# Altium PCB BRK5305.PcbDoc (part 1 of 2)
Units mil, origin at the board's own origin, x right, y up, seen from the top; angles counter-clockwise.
Board outline 4724.41 x 3149.61 mil, 4 copper layers (L1-Top, L2-Plane-1, L3-Plane-2, L4-Bottom), stack 60.6 mil thick; 66 components, 156 nets, 613 pads, 306 vias.
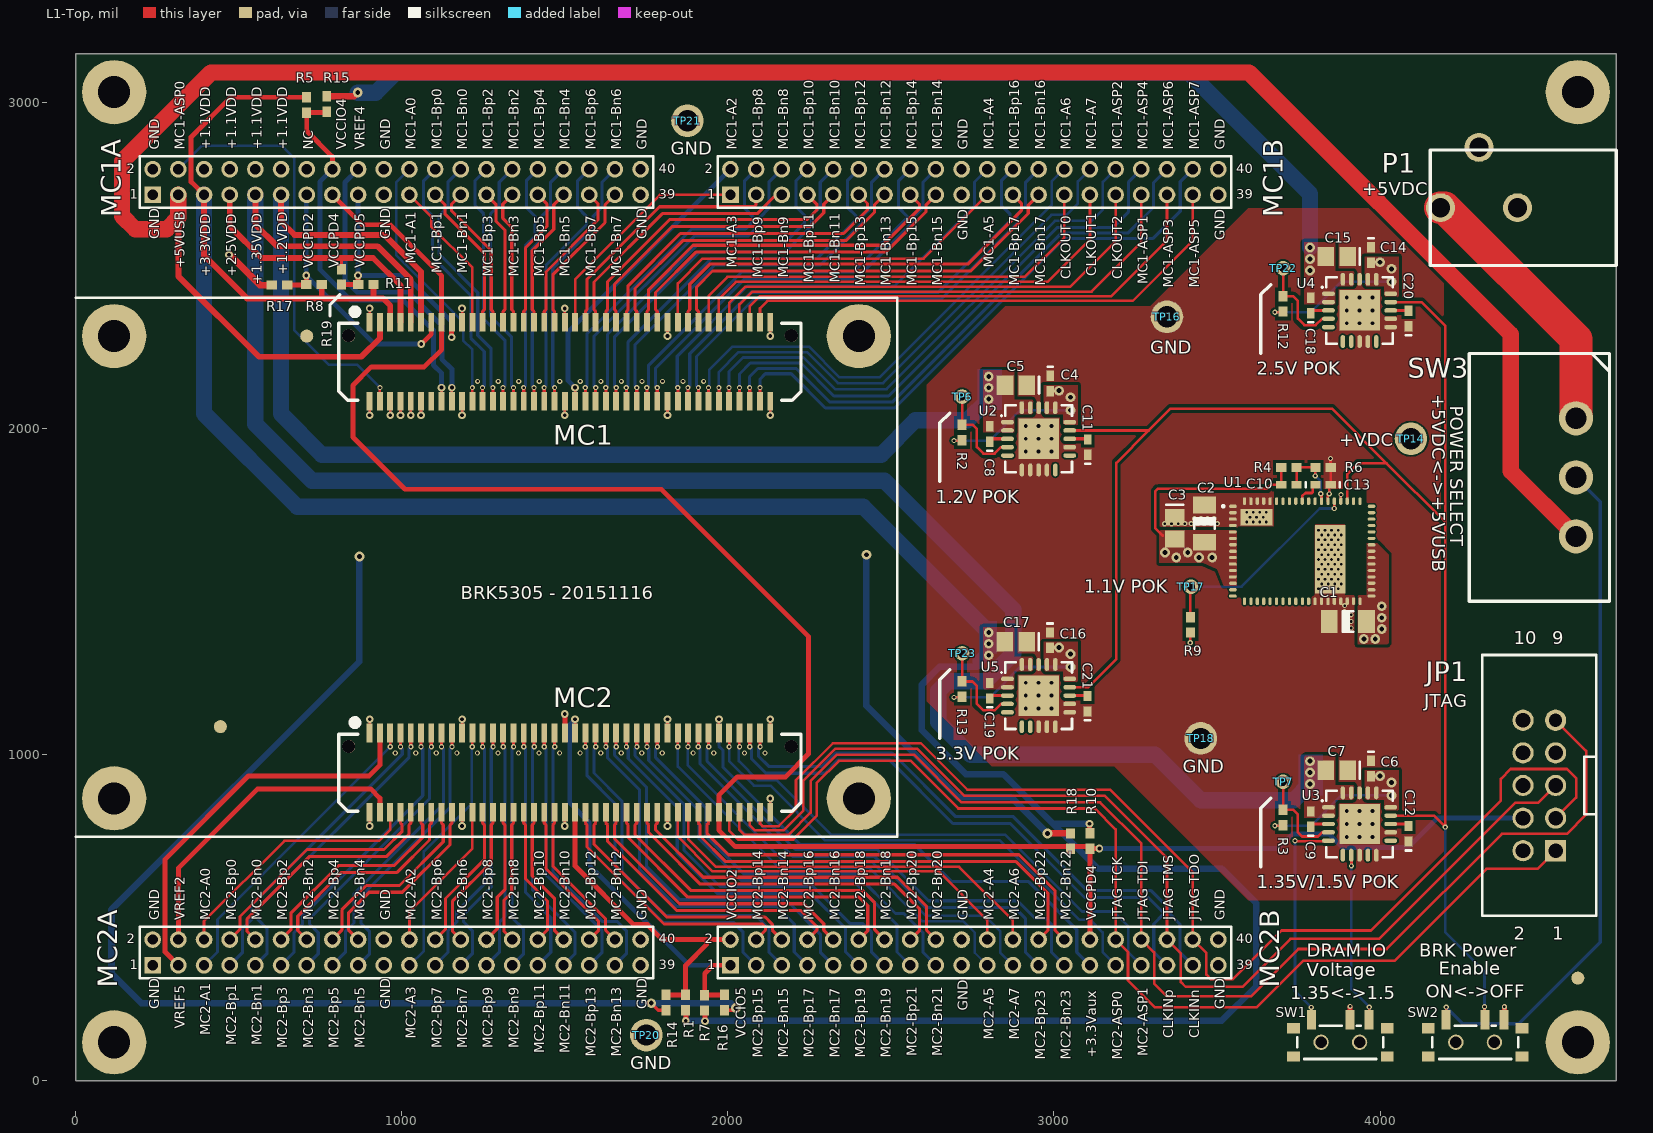
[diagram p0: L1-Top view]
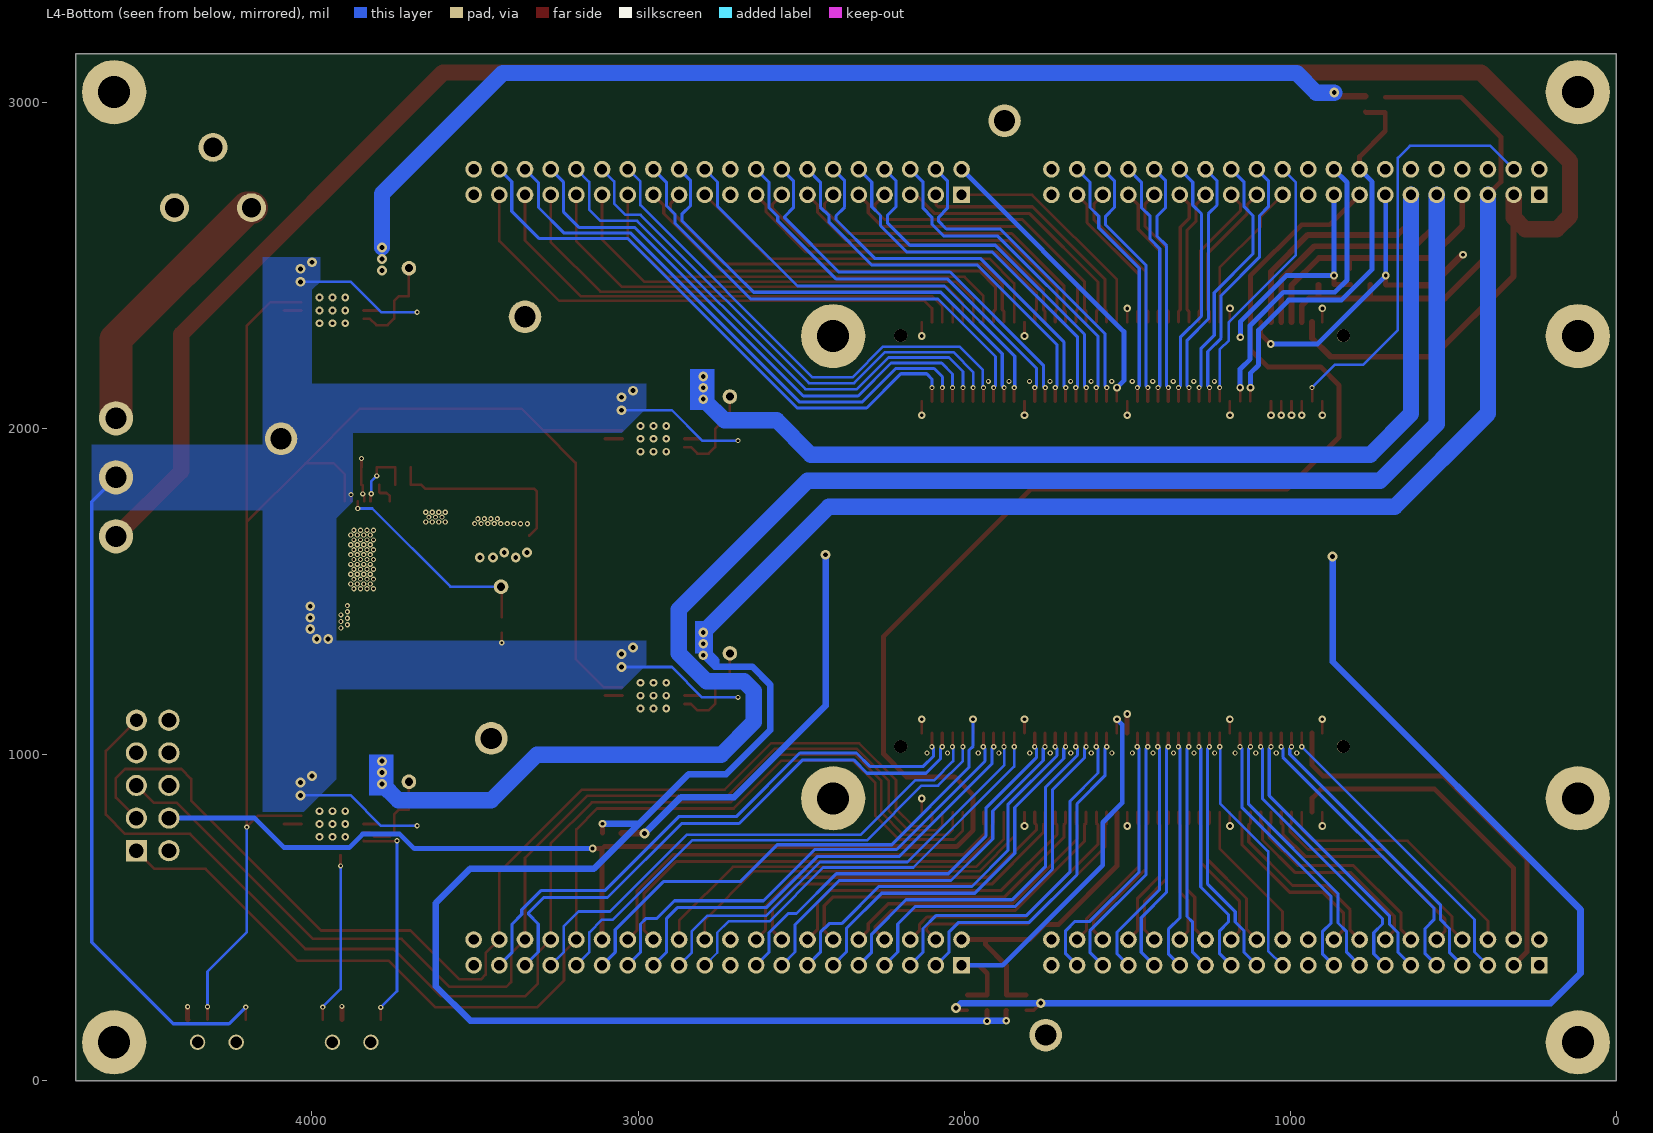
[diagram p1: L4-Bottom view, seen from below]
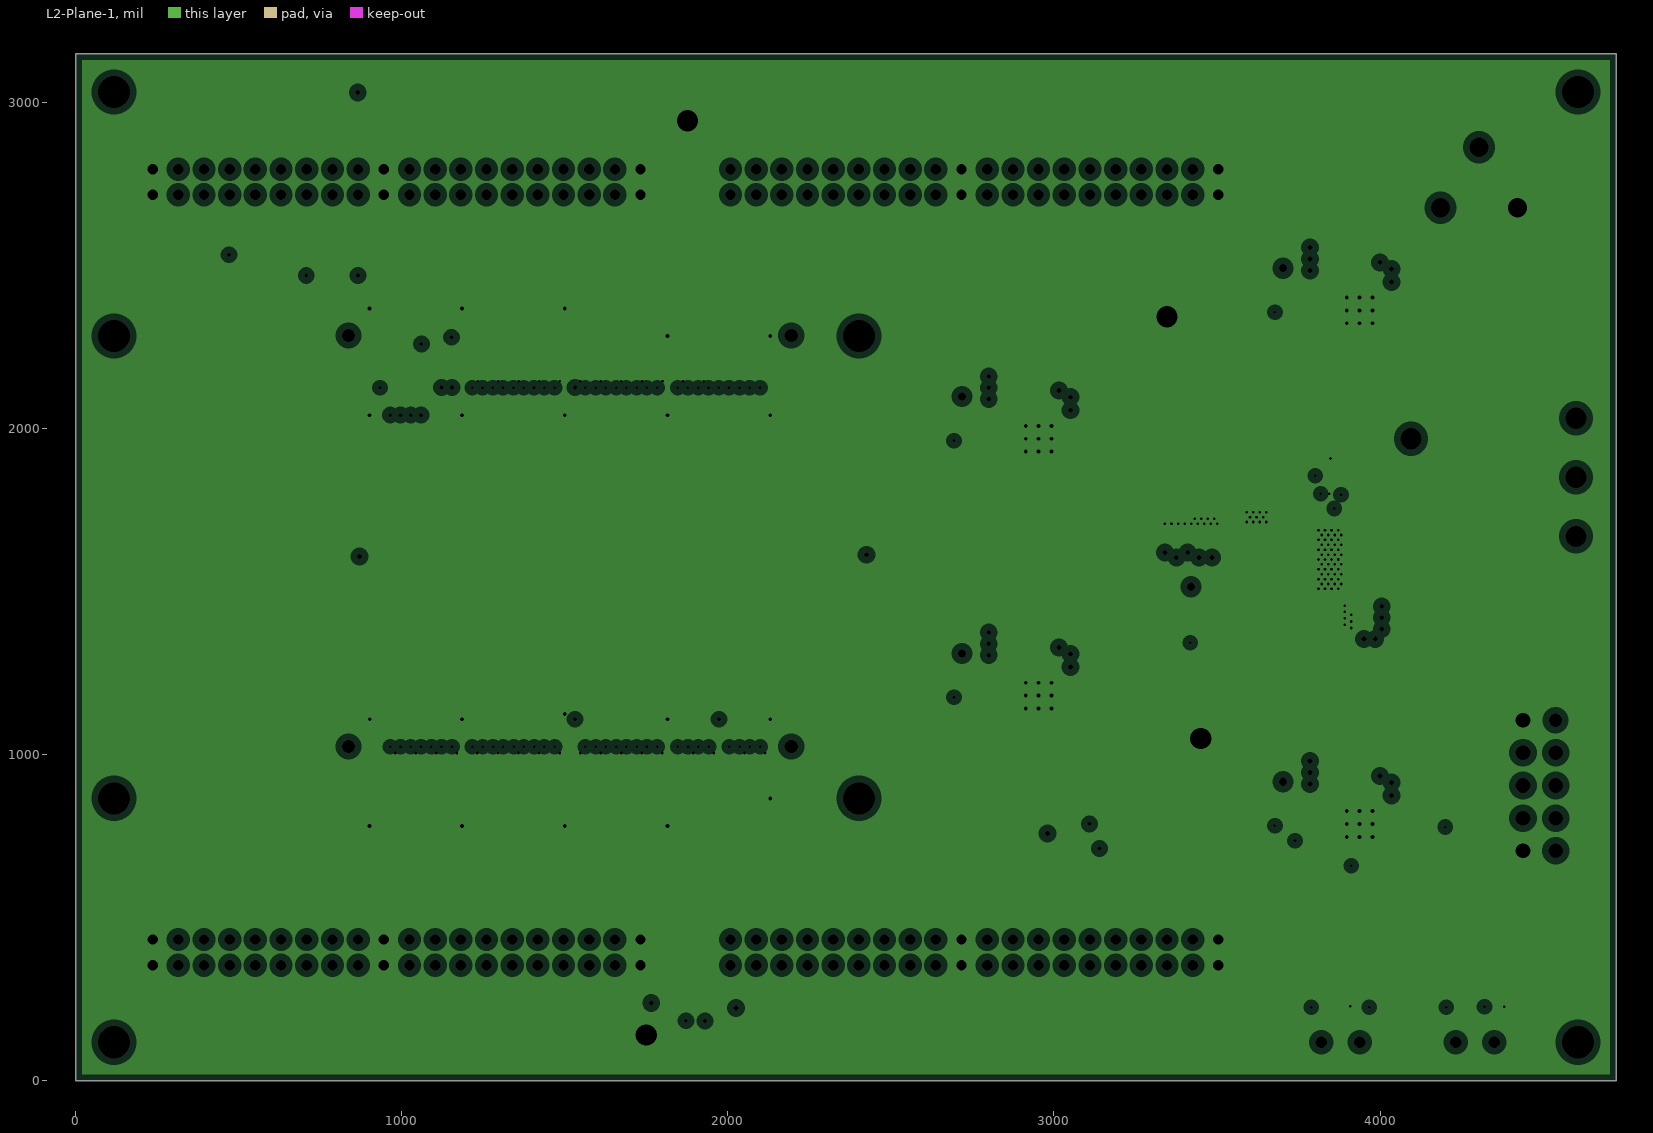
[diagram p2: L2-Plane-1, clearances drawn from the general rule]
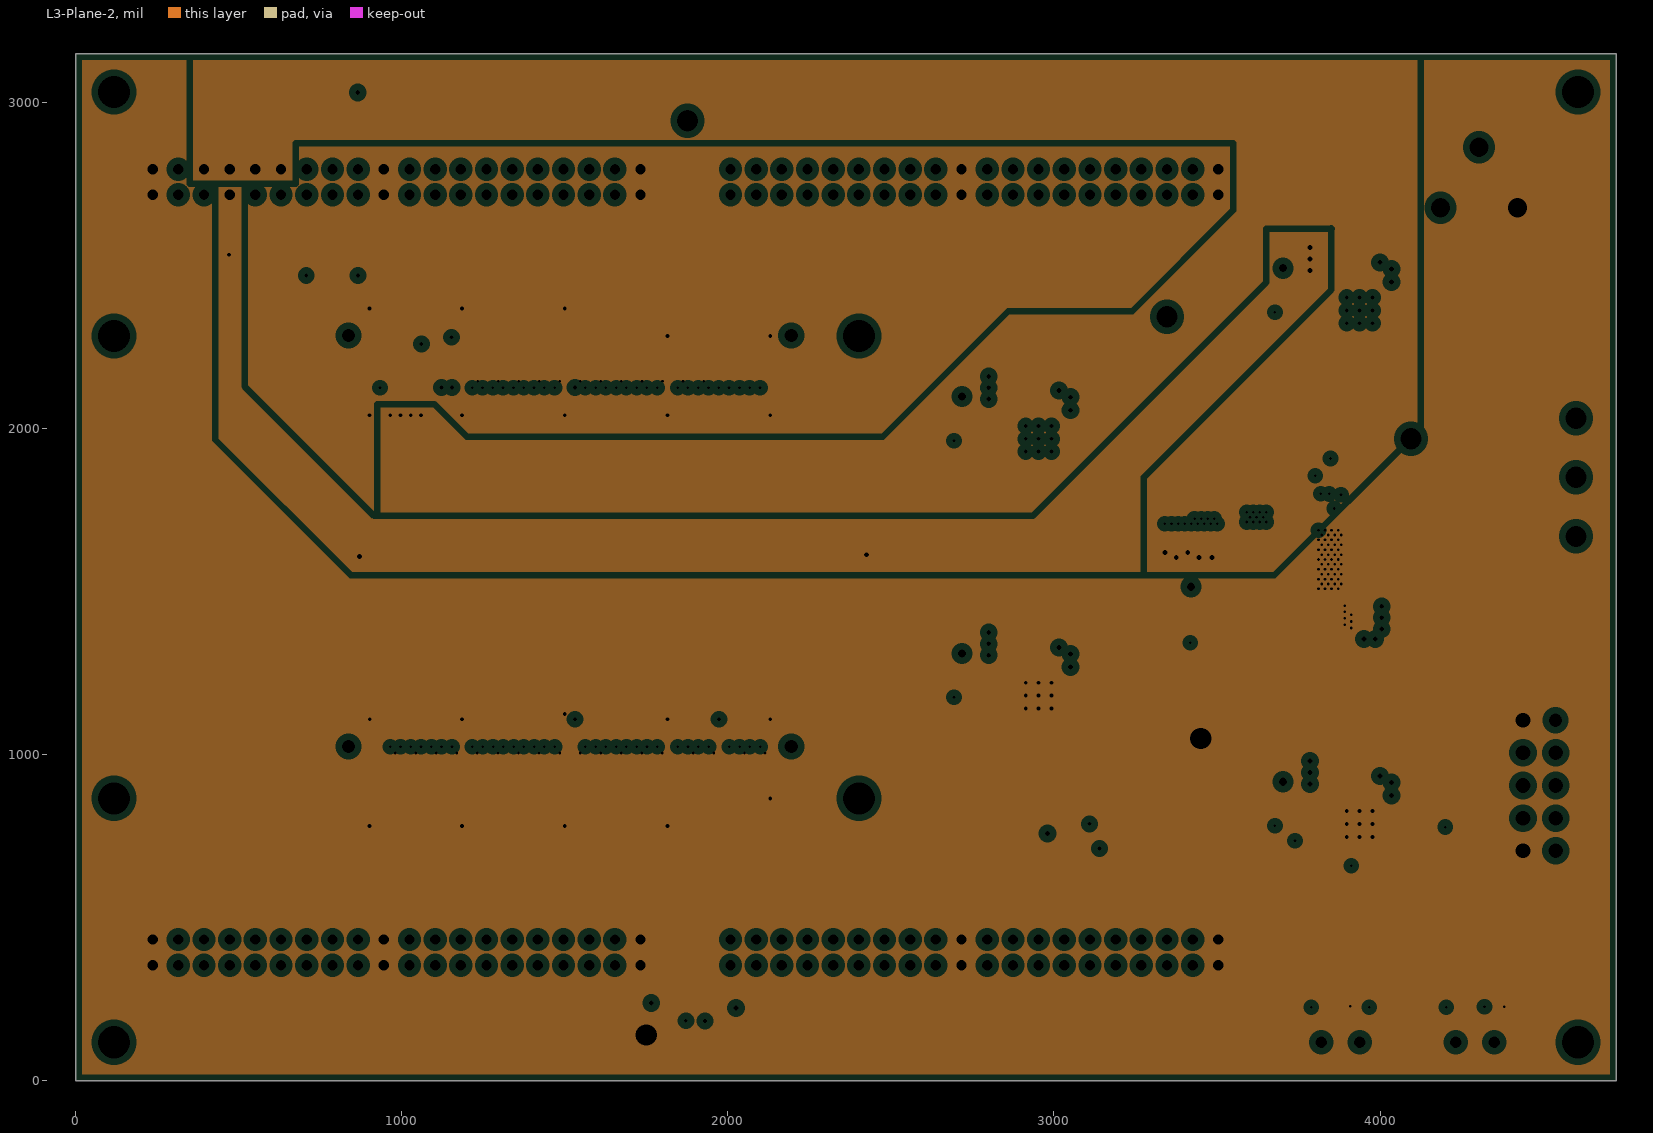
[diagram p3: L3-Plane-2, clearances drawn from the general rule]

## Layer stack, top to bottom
Top Solder: solder mask 0.4, Solder Resist, Dk 3.5
L1-Top: signal copper 2.1
Dielectric1: prepreg 7.3, 370HR, Dk 4.2
L2-Plane-1: plane copper 1.4, net DGND
Dielectric 3: core 39, 370HR, Dk 4.2
L3-Plane-2: plane copper 1.4, net (Multiple Nets)
Dielectric 2: prepreg 7.3, 370HR, Dk 4.2
L4-Bottom: signal copper 2.1
Bottom Solder: solder mask 0.4, Solder Resist, Dk 3.5

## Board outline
0,0 4724.41,0 4724.41,3149.61 0,3149.61

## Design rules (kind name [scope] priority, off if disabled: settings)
Clearance okxClearancePour [((InPolygon) AND (OnLayer('L1-Top') OR OnLayer('L2-Bottom')) ) vs ((InAnyNet) AND (OnLayer('L1-Top') OR OnLayer('L2-Bottom')) )] p1: gap=10
Clearance Fiducial [All vs ((Not PadIsPlated) And (HoleSize = 0))] p2: gap=25
Clearance [All] p3: gap=5
DiffPairsRouting okxDiffRouting100ohm [All] p1: maxlimit=11.5 minlimit=11.5 mostfreqgap=11.5 toplayer_minwidth=9.5 toplayer_maxwidth=9.5 toplayer_prefwidth=9.5 bottomlayer_minwidth=9.5 bottomlayer_maxwidth=9.5 bottomlayer_prefwidth=9.5 maxuncoupledlength=500
FabricationTestPointUsage TestPointUsage [All] p1: valid=0 allowmultiple=FALSE
FabricationTestpoint Testpoint [All] p1: side=3 testpointundercomponent=TRUE minsize=40 maxsize=100 preferedsize=60 minholesize=0 maxholesize=40 preferedholesize=32 testpointgrid=1 allowsidetop=TRUE allowsidebottom=TRUE usegrid=TRUE gridtolerance=0.01
HoleSize [All] p1: absolutevalues=TRUE maxlimit=100 minlimit=8 maxpercent=80.000 minpercent=20.000
PlaneClearance [All] p1: clearance=20
PlaneConnect [All] p1: planeconnectstyle=Direct reliefexpansion=20 reliefentries=4 reliefconductorwidth=10 reliefairgap=10
PolygonConnect "Via Connect" [IsVia] p1: connectstyle=Direct reliefconductorwidth=10 reliefentries=4 polygonreliefangle="90 Angle" airgapwidth=10
PolygonConnect [All] p2: connectstyle=Direct reliefconductorwidth=10 reliefentries=4 polygonreliefangle="90 Angle" airgapwidth=10
RoutingVias [All] p1: holewidth=8 width=16 viastyle="Through Hole" minholewidth=8 minwidth=16 maxholewidth=25 maxwidth=50
SolderMaskExpansion [All] p1: expansion=4
Width okWidth50ohm [All] p1: maxlimit=200 minlimit=8 preferedwidth=12 minimp=50.000000 maximp=50.000000 favimp=50.000000
24 further rules are at their usual default settings.

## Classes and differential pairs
net class okPower: +1.1VDD +1.2VDD +1.35VDD +2.5VDD +3.3VAUX +3.3VDD +5VDC +5VUSB +VDC DGND VCCIO2 VCCIO4 VCCIO5 VCCPD2 VCCPD4 VCCPD5 VREF2 VREF4 VREF5
net class okMC1-A: MC1-A0 MC1-A1 MC1-A2 MC1-A3 MC1-A4 MC1-A5 MC1-A6 MC1-A7
net class okMC1-ASP: MC1-ASP0 MC1-ASP1 MC1-ASP2 MC1-ASP3 MC1-ASP4 MC1-ASP5 MC1-ASP6 MC1-ASP7
net class okMC1-B: MC1-BN0 MC1-BN1 MC1-BN2 MC1-BN3 MC1-BN4 MC1-BN5 MC1-BN6 MC1-BN7 MC1-BN8 MC1-BN9 MC1-BN10 MC1-BN11 MC1-BN12 MC1-BN13 MC1-BN14 MC1-BN15 MC1-BN16 MC1-BN17 MC1-BP0 MC1-BP1 MC1-BP2 MC1-BP3 MC1-BP4 MC1-BP5 MC1-BP6 MC1-BP7 MC1-BP8 MC1-BP9 MC1-BP10 MC1-BP11 MC1-BP12 MC1-BP13 MC1-BP14 MC1-BP15 MC1-BP16 MC1-BP17
net class okMC-CLK: CLKINN CLKINP CLKOUT0 CLKOUT1 CLKOUT2
net class okJTAG: JTAG_TCK JTAG_TDI JTAG_TDO JTAG_TMS
net class okMC2-B: MC2-BN0 MC2-BN1 MC2-BN2 MC2-BN3 MC2-BN4 MC2-BN5 MC2-BN6 MC2-BN7 MC2-BN8 MC2-BN9 MC2-BN10 MC2-BN11 MC2-BN12 MC2-BN13 MC2-BN14 MC2-BN15 MC2-BN16 MC2-BN17 MC2-BN18 MC2-BN19 MC2-BN20 MC2-BN21 MC2-BN22 MC2-BN23 MC2-BP0 MC2-BP1 MC2-BP2 MC2-BP3 MC2-BP4 MC2-BP5 MC2-BP6 MC2-BP7 MC2-BP8 MC2-BP9 MC2-BP10 MC2-BP11 MC2-BP12 MC2-BP13 MC2-BP14 MC2-BP15 MC2-BP16 MC2-BP17 MC2-BP18 MC2-BP19 MC2-BP20 MC2-BP21 MC2-BP22 MC2-BP23
net class okMC2-ASP: MC2-ASP0 MC2-ASP1
differential pair D_CLKIN: +CLKINP -CLKINN
differential pair D_MC2-B23: +MC2-BP23 -MC2-BN23
differential pair D_MC2-B22: +MC2-BP22 -MC2-BN22
differential pair D_MC2-B21: +MC2-BP21 -MC2-BN21
differential pair D_MC2-B20: +MC2-BP20 -MC2-BN20
differential pair D_MC2-B19: +MC2-BP19 -MC2-BN19
differential pair D_MC2-B18: +MC2-BP18 -MC2-BN18
differential pair D_MC2-B17: +MC2-BP17 -MC2-BN17
differential pair D_MC2-B16: +MC2-BP16 -MC2-BN16
differential pair D_MC2-B15: +MC2-BP15 -MC2-BN15
differential pair D_MC2-B14: +MC2-BP14 -MC2-BN14
differential pair D_MC2-B13: +MC2-BP13 -MC2-BN13
differential pair D_MC2-B12: +MC2-BP12 -MC2-BN12
differential pair D_MC2-B11: +MC2-BP11 -MC2-BN11
differential pair D_MC2-B10: +MC2-BP10 -MC2-BN10
differential pair D_MC2-B9: +MC2-BP9 -MC2-BN9
differential pair D_MC2-B8: +MC2-BP8 -MC2-BN8
differential pair D_MC2-B7: +MC2-BP7 -MC2-BN7
differential pair D_MC2-B6: +MC2-BP6 -MC2-BN6
differential pair D_MC2-B5: +MC2-BP5 -MC2-BN5
differential pair D_MC2-B4: +MC2-BP4 -MC2-BN4
differential pair D_MC2-B3: +MC2-BP3 -MC2-BN3
differential pair D_MC2-B2: +MC2-BP2 -MC2-BN2
differential pair D_MC2-B1: +MC2-BP1 -MC2-BN1
differential pair D_MC2-B0: +MC2-BP0 -MC2-BN0
differential pair D_MC1-B17: +MC1-BP17 -MC1-BN17
differential pair D_MC1-B16: +MC1-BP16 -MC1-BN16
differential pair D_MC1-B15: +MC1-BP15 -MC1-BN15
differential pair D_MC1-B14: +MC1-BP14 -MC1-BN14
differential pair D_MC1-B13: +MC1-BP13 -MC1-BN13
differential pair D_MC1-B12: +MC1-BP12 -MC1-BN12
differential pair D_MC1-B11: +MC1-BP11 -MC1-BN11
differential pair D_MC1-B10: +MC1-BP10 -MC1-BN10
differential pair D_MC1-B9: +MC1-BP9 -MC1-BN9
differential pair D_MC1-B8: +MC1-BP8 -MC1-BN8
differential pair D_MC1-B7: +MC1-BP7 -MC1-BN7
differential pair D_MC1-B6: +MC1-BP6 -MC1-BN6
differential pair D_MC1-B5: +MC1-BP5 -MC1-BN5
differential pair D_MC1-B4: +MC1-BP4 -MC1-BN4
differential pair D_MC1-B3: +MC1-BP3 -MC1-BN3
differential pair D_MC1-B2: +MC1-BP2 -MC1-BN2
differential pair D_MC1-B1: +MC1-BP1 -MC1-BN1
differential pair D_MC1-B0: +MC1-BP0 -MC1-BN0

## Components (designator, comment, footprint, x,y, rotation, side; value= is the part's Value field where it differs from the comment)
C1 "JMK316BJ476ML-T" CAPC3216N 3901.2,1407.89 r0 top
C2 "JMK316BJ476ML-T" CAPC3216N 3461.04,1708.47 r270 top
C3 "LMK212BJ106KG-T" CAPC2012N 3370.2,1694.89 r270 top
C4 "LMK105BJ105KV-F" CAPC1005N 2988.23,2138.07 r270 top
C5 "LMK212BJ106KG-T" CAPC2012N 2883.23,2133.07 r180 top
C6 "LMK105BJ105KV-F" CAPC1005N 3972.01,957.4 r270 top
C7 "LMK212BJ106KG-T" CAPC2012N 3867.01,952.4 r180 top
C8 "C0402C221J5GACTU" CAPC1005N 2803.23,1983.07 r90 top
C9 "C0402C221J5GACTU" CAPC1005N 3787.01,802.4 r90 top
C10 "C0402C330J5GACTU" CAPC1005N 3720.2,1827.89 r180 top
C11 "C0402C103K4RACTU" CAPC1005N 3103.23,1943.07 r90 top
C12 "C0402C103K4RACTU" CAPC1005N 4087.01,757.4 r90 top
C13 "EMK105BJ473KV-F" CAPC1005N 3825.2,1827.89 r180 top
C14 "LMK105BJ105KV-F" CAPC1005N 3972.01,2532.2 r270 top
C15 "LMK212BJ106KG-T" CAPC2012N 3867.01,2527.2 r180 top
C16 "LMK105BJ105KV-F" CAPC1005N 2987.76,1351.1 r270 top
C17 "LMK212BJ106KG-T" CAPC2012N 2882.76,1346.1 r180 top
C18 "C0402C221J5GACTU" CAPC1005N 3787.01,2377.2 r90 top
C19 "C0402C221J5GACTU" CAPC1005N 2802.76,1196.1 r90 top
C20 "C0402C103K4RACTU" CAPC1005N 4087.01,2337.2 r90 top
C21 "C0402C103K4RACTU" CAPC1005N 3102.76,1156.1 r90 top
JP1 "70246-1004" HDR2X5-SHRD 4488.19,905.51 r90 top
MC1 "BTE-040-01-F-D-A" BTE-040 1515.75,2204.73 r0 top locked
MC1A "0877584016" HDR2X20-2MM 984.25,2755.91 r0 top locked
MC1B "0877584016" HDR2X20-2MM 2755.91,2755.91 r0 top locked
MC2 "BTE-040-01-F-D-A" BTE-040 1515.75,944.88 r0 top locked
MC2A "0877584016" HDR2X20-2MM 984.25,393.7 r0 top locked
MC2B "0877584016" HDR2X20-2MM 2755.91,393.7 r0 top locked
P1 "PJ-102AH" CUI-PJ102A 4724.41,2677.17 r90 top
R1 "CRCW04020000Z0ED" RESC1005N 1870,240 r270 top
R2 "CRCW040210K0JNED" RESC1005N 2718.23,1988.07 r270 top
R3 "CRCW040210K0JNED" RESC1005N 3702.01,807.4 r270 top
R4 "CRCW0402150KFKED" RESC1005N 3720.2,1880.89 r180 top
R5 "CRCW04020000Z0ED" RESC1005N 708.66,2992.13 r90 top
R6 "CRCW0402178KFKED" RESC1005N 3825.2,1880.89 r180 top
R7 "CRCW04020000Z0ED" RESC1005N 1929,239 r270 top
R8 "CRCW04020000Z0ED" RESC1005N 731,2441 r0 top
R9 "CRCW040210K0JNED" RESC1005N 3418,1398 r270 top
R10 "CRCW04020000Z0ED" RESC1005N 3110,735 r90 top
R11 "CRCW04020000Z0ED" RESC1005N 890,2441 r0 top
R12 "CRCW040210K0JNED" RESC1005N 3702.01,2382.2 r270 top
R13 "CRCW040210K0JNED" RESC1005N 2717.76,1201.1 r270 top
R14 "CRCW04020000Z0ED" RESC1005N 1810,240 r90 top
R15 "CRCW04020000Z0ED" RESC1005N 770,2995 r270 top
R16 "CRCW04020000Z0ED" RESC1005N 1990,240 r90 top
R17 "CRCW04020000Z0ED" RESC1005N 625,2440 r0 top
R18 "CRCW04020000Z0ED" RESC1005N 3050,735 r270 top
R19 "CRCW04020000Z0ED" RESC1005N 815,2465 r270 top
SW1 "SSSS811101" SSSS811101 3877.95,118.11 r0 top
SW2 "SSSS811101" SSSS811101 4291.34,118.11 r0 top
SW3 "L102011MS02Q" L102011MS 4488.19,1850.39 r180 top
TP6 "1.2V POK" TP_SMALL 2718.23,2098.07 r0 top
TP7 "1.35V/1.5V POK" TP_SMALL 3702.48,916.97 r0 top
TP14 "+VDC" TP_MED 4094.49,1968.5 r90 top
TP16 "GND" TP_MED 3346.46,2342.52 r90 top
TP17 "1.1V POK" TP_SMALL 3420,1515 r90 top
TP18 "GND" TP_MED 3450,1050 r90 top
TP20 "GND" TP_MED 1750,140 r90 top
TP21 "GND" TP_MED 1876,2944 r90 top
TP22 "2.5V POK" TP_SMALL 3702.48,2491.77 r90 top
TP23 "3.3V POK" TP_SMALL 2718.23,1310.67 r90 top
U1 "EN5364QI" EN5364 3761.2,1623.89 r0 top
U2 "TPS7A7100RGWT" S-PVQN-N20 2952.76,1968.5 r0 top
U3 "TPS7A7100RGWT" S-PVQN-N20 3937.01,787.4 r0 top
U4 "TPS7A7100RGWT" S-PVQN-N20 3937.01,2362.2 r0 top
U5 "TPS7A7100RGWT" S-PVQN-N20 2952.76,1181.1 r0 top

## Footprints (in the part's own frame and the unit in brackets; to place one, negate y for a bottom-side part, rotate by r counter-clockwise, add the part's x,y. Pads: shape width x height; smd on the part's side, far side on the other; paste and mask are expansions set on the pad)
BTE-040 [mm] "0.8mm Samtech socket"
  rect 0.46x1.45 smd: 1(-15.6,3.085) 2(-15.6,-3.085) 3(-14.8,3.085) 4(-14.8,-3.085) 5(-14,3.085) 6(-14,-3.085) 7(-13.2,3.085) 8(-13.2,-3.085) 9(-12.4,3.085) 10(-12.4,-3.085) 11(-11.6,3.085) 12(-11.6,-3.085) 13(-10.8,3.085) 14(-10.8,-3.085) 15(-10,3.085) 16(-10,-3.085) 17(-9.2,3.085) 18(-9.2,-3.085) 19(-8.4,3.085) 20(-8.4,-3.085) 21(-7.6,3.085) 22(-7.6,-3.085) 23(-6.8,3.085) 24(-6.8,-3.085) 25(-6,3.085) 26(-6,-3.085) 27(-5.2,3.085) 28(-5.2,-3.085) 29(-4.4,3.085) 30(-4.4,-3.085) 31(-3.6,3.085) 32(-3.6,-3.085) 33(-2.8,3.085) 34(-2.8,-3.085) 35(-2,3.085) 36(-2,-3.085) 37(-1.2,3.085) 38(-1.2,-3.085) 39(-0.4,3.085) 40(-0.4,-3.085) 41(0.4,3.085) 42(0.4,-3.085) 43(1.2,3.085) 44(1.2,-3.085) 45(2,3.085) 46(2,-3.085) 47(2.8,3.085) 48(2.8,-3.085) 49(3.6,3.085) 50(3.6,-3.085) 51(4.4,3.085) 52(4.4,-3.085) 53(5.2,3.085) 54(5.2,-3.085) 55(6,3.085) 56(6,-3.085) 57(6.8,3.085) 58(6.8,-3.085) 59(7.6,3.085) 60(7.6,-3.085) 61(8.4,3.085) 62(8.4,-3.085) 63(9.2,3.085) 64(9.2,-3.085) 65(10,3.085) 66(10,-3.085) 67(10.8,3.085) 68(10.8,-3.085) 69(11.6,3.085) 70(11.6,-3.085) 71(12.4,3.085) 72(12.4,-3.085) 73(13.2,3.085) 74(13.2,-3.085) 75(14,3.085) 76(14,-3.085) 77(14.8,3.085) 78(14.8,-3.085) 79(15.6,3.085) 80(15.6,-3.085)
  round 1.02 hole 1.02: 81(-17.235,2.035) 82(17.235,2.035)
  silkscreen extent -18,-3 18,4.15
CAPC1005N [mm] "Chip Capacitor, Body 1.0x0.5mm, IPC Medium Density"
  rect 0.8x0.6 smd: 1(-0.6,0) 2(0.6,0)
  silkscreen extent -1.3,-0.2 -1.3,0.2, body extent -0.55,-0.3 0.55,0.3, height 0.6
CAPC2012N [mm] "Chip Capacitor, Body 2.0x1.3mm, IPC Medium Density"
  rect 1.3x1.5 smd: 1(-0.85,0) 2(0.85,0)
  silkscreen extent -1.8,-0.65 -1.8,0.65, body extent -1.1,-0.72 1.1,0.72, height 1.1
CAPC3216N [mm] "Chip Capacitor, Body 3.2x1.6mm, IPC Medium Density"
  rect 1.3x1.8 smd: 1(-1.45,0) 2(1.45,0)
  silkscreen extent -0.4,-0.8 0.4,0.8, body extent -1.7,-0.9 1.7,0.9, height 1.35
CUI-PJ102A [mm] "2.1mm/5.5mm DC power jack"
  round 2.25 hole 1.5: 1(0,13.7) 2(0,7.7) 3(4.7,10.7)
  silkscreen extent -4.5,0 4.5,14.5
EN5364 [mm] "6A Voltage Mode Synchronous Buck PWM  DC-DC Converter"
  oval 0.6x0.25 smd mask+0.076: 1(-5.4,3.5) 2(-5.4,3) 3(-5.4,2.5) 4(-5.4,2) 5(-5.4,1.5) 6(-5.4,1) 7(-5.4,0.5) 8(-5.4,0) 9(-5.4,-0.5) 10(-5.4,-1) 11(-5.4,-1.5) 12(-5.4,-2) 13(-5.4,-2.5) 14(-5.4,-3) 15(-5.4,-3.5) 35(5.4,-3.5) 36(5.4,-3) 37(5.4,-2.5) 38(5.4,-2) 39(5.4,-1.5) 40(5.4,-1) 41(5.4,-0.5) 42(5.4,0) 43(5.4,0.5) 44(5.4,1) 45(5.4,1.5) 46(5.4,2) 47(5.4,2.5) 48(5.4,3) 49(5.4,3.5)
  oval 0.25x0.6 smd mask+0.076: 16(-4.5,-3.9) 17(-4,-3.9) 18(-3.5,-3.9) 19(-3,-3.9) 20(-2.5,-3.9) 21(-2,-3.9) 22(-1.5,-3.9) 23(-1,-3.9) 24(-0.5,-3.9) 25(0.025,-3.9) 26(0.5,-3.9) 27(1,-3.9) 28(1.5,-3.9) 29(2,-3.9) 30(2.5,-3.9) 31(3,-3.9) 32(3.5,-3.9) 33(4,-3.9) 34(4.5,-3.9) 50(4.5,3.9) 51(4,3.9) 52(3.5,3.9) 53(3,3.9) 54(2.5,3.9) 55(2,3.9) 56(1.5,3.9) 57(1,3.9) 58(0.5,3.9) 59(0,3.9) 60(-0.5,3.9) 61(-1,3.9) 62(-1.5,3.9) 63(-2,3.9) 64(-2.5,3.9) 65(-3,3.9) 66(-3.5,3.9) 67(-4,3.9) 68(-4.5,3.9)
  rect 2.35x5.35 smd paste-1.5 mask+0.076: 69(2.175,-0.625)
  rect 2.5x1.3 smd paste-1.5 mask+0.076: 70(-3.55,2.65)
  silkscreen extent -6.2,3.45 -6.1,3.55
HDR2X5-SHRD [mil] "0.1\" 2x5 shrouded header"
  rect 65x65 hole 44.88: 1(-200,-50)
  round 65 hole 44.88: 2(-200,50) 3(-100,-50) 4(-100,50) 5(0,-50) 6(0,50) 7(100,-50) 8(100,50) 10(200,50)
  round 65 hole 40: 9(200,-50)
  silkscreen extent -400,-175 400,175
HDR2X20-2MM [mm] "2mm 2x20 header"
  rect 1.3x1.3 hole 0.8: 1(-19,-1)
  round 1.3 hole 0.8: 2(-19,1) 3(-17,-1) 4(-17,1) 5(-15,-1) 6(-15,1) 7(-13,-1) 8(-13,1) 9(-11,-1) 10(-11,1) 11(-9,-1) 12(-9,1) 13(-7,-1) 14(-7,1) 15(-5,-1) 16(-5,1) 17(-3,-1) 18(-3,1) 19(-1,-1) 20(-1,1) 21(1,-1) 22(1,1) 23(3,-1) 24(3,1) 25(5,-1) 26(5,1) 27(7,-1) 28(7,1) 29(9,-1) 30(9,1) 31(11,-1) 32(11,1) 33(13,-1) 34(13,1) 35(15,-1) 36(15,1) 37(17,-1) 38(17,1) 39(19,-1) 40(19,1)
  silkscreen extent -20,-2 20,2
L102011MS [mil]
  round 105 hole 65: 1(-112.5,-181) 2(-112.5,0) 3(-112.5,181)
  silkscreen extent -215,-380 215,380
RESC1005N [mm] "Chip Resistor, Body 1.1x0.5mm, IPC Medium Density"
  rect 0.8x0.7 smd: 1(-0.6,0) 2(0.6,0)
  body extent -0.55,-0.3 0.55,0.3, height 0.4
S-PVQN-N20 [mm]
  rect 3.15x3.15 smd paste-4: 0(0,0)
  rrect100% 1x0.35 smd mask+0.07: 1(-2.425,1.3) 2(-2.425,0.65) 3(-2.425,0) 4(-2.425,-0.65) 5(-2.425,-1.3) 11(2.425,-1.3) 12(2.425,-0.65) 13(2.425,0) 14(2.425,0.65) 15(2.425,1.3)
  rrect100% 0.35x1 smd mask+0.07: 6(-1.3,-2.425) 7(-0.65,-2.425) 8(0,-2.425) 9(0.65,-2.425) 10(1.3,-2.425) 16(1.3,2.425) 17(0.65,2.425) 18(0,2.425) 19(-0.65,2.425) 20(-1.3,2.425)
  silkscreen extent -2.9,-2.6 2.6,2.6, body extent -2.07,-2.07 2.07,2.07, height 0.8
SSSS811101 [mm] "Surface mount, 1 position, 2 pole switch"
  rect 1x0.8 smd: 0(-3.65,-1.1) 0(-3.65,1.1) 0(3.65,-1.1) 0(3.65,1.1)
  round 1.2 hole 0.9: 0(-1.5,0) 0(1.5,0)
  rect 0.7x1.5 smd: 1(-2.25,1.75) 2(0.75,1.75) 3(2.25,1.75)
  silkscreen extent -3.35,-1.3 3.35,1.3
TP_MED [mil] "Testpoint - medium sized"
  round 100 hole 65: 1(0,0)
TP_SMALL [mil]
  round 45 hole 25: 1(0,0)

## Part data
C1 C2: library part 000570, "Ceramic Capacitor"
C3 C5 C7 C15 C17: library part 000491, "Ceramic capacitor"
C4 C6 C14 C16: library part 000480, "Ceramic capacitor"
C8 C9 C18 C19: library part 001219, "Ceramic capacitor"
C10: library part 000935, "Ceramic capacitor"
C11 C12 C20 C21: library part 000295, "Ceramic Capacitor"
C13: library part 000335, "Ceramic Capacitor"
JP1: library part 000777, "2.54mm, 10 Pos, Dual Row Header"
MC1 MC2: library part 000059, "0.8mm high-density header"
MC1A MC1B MC2A MC2B: library part 000583, "2mm header, 20x2, thru-hole"
P1: library part 000356, "DC power connector - high current"
R1 R5 R7 R8 R10 R11 R14 R15 R16 R17 R18 R19: library part 000755, "Thick-film resistor"
R2 R3 R9 R12 R13: library part 000759, "Thick-film resistor"
R4: library part 000796, "Thick-film resistor"
R6: library part 001310, "Thick-film resistor"
SW1 SW2: library part 000231, "Slide"
SW3: library part 001220, "SPDT"
TP6 TP7 TP14 TP16 TP17 TP18 TP20 TP21 TP22 TP23: library part 000812, "Testpoint."
U1: library part 000576, "6A Synchronous Buck DC-DC converter"
U2 U3 U4 U5: library part 001209, "LDO voltage regulator"

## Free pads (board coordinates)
  round 196.85 hole 98.43: 0(118.11,118.11) 0(118.11,866.14) 0(118.11,2283.47) 0(118.11,3031.5) 0(2401.58,866.14) 0(2401.58,2283.47) 0(4606.3,118.11) 0(4606.3,3031.5)
  round 40 smd mask+20: FD0(444,1086) FD0(708.66,2283.46) FD0(4606.3,314.96)

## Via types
v1: diameter 16, hole 8, L1-Top to L4-Bottom, tented both sides, 140 vias
v2: diameter 23.62, hole 11.81, L1-Top to L4-Bottom, tented both sides, 74 vias
v3: diameter 15.99, hole 8, L1-Top to L4-Bottom, tented both sides, 52 vias
v4: diameter 30, hole 15, L1-Top to L4-Bottom, tented both sides, 40 vias

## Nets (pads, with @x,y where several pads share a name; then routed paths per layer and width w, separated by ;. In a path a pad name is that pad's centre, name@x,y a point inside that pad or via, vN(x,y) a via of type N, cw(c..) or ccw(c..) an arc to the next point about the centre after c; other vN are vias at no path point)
+1.1VDD: C2.2 C3.2 C10.2 MC1.6 MC1.8 MC1.10 MC1.12 MC1A.6 MC1A.8 MC1A.10 MC1A.12 R4.2 U1.5 U1.6 U1.7 U1.8 U1.9 U1.10 U1.11 U1.12 U1.13 | length 762
  L1-Top w8: v2(964.57,2040.99) MC1.6@964.57,2083.27 ; v2(996.06,2040.99) MC1.8@996.06,2083.27 ; v2(1027.56,2040.99) MC1.10@1027.56,2083.27 ; v2(1059.06,2040.99) MC1.12@1059.06,2083.27 ; 3333.2,1671.89 3310.2,1694.89 3310.2,1807.47 3318.2,1815.47 3652.77,1815.47 3665.2,1827.89 C10.2@3696.58,1827.89 R4.2@3696.58,1880.89
  other v4: 3375,1605 3445,1605 3485,1605 3340,1620 3410,1620
+1.2VDD: C5.2 C8.2 MC1.11 MC1A.11 U2.1 U2.2 U2.19 U2.20 | length 3693
  L1-Top w18: MC1A.11@629.92,2716.54 629.92,2635.08 671,2594 946,2594 1059.06,2480.94 MC1.11@1059.06,2326.18
  L4-Bottom w50: MC1A.11@629.92,2716.54 629.92,2045.08 755,1920 2470,1920 2575,2025 2735,2025 v4(2800,2090)
  other v4: 2800,2125 2800,2160
+1.35VDD: C7.2 C9.2 MC1.9 MC1A.9 U3.1 U3.2 U3.19 U3.20 | length 5798
  L1-Top w18: MC1A.9@551.18,2716.54 551.18,2625.82 618,2559 926,2559 1027.56,2457.44 MC1.9@1027.56,2326.18
  L4-Bottom w50: MC1A.9@551.18,2716.54 551.18,2013.82 725,1840 2480,1840 2875,1445 2875,1310 2790,1225 2675,1225 2645,1195 2645,1100 2745,1000 3310,1000 3450,860 3735,860 v4(3785,910)
  other v4: 3785,945 3785,980
+2.5VDD: C15.2 C18.2 MC1.7 MC1A.7 R14.1 R15.1 R16.1 R17.1 R18.1 R19.1 U4.1 U4.2 U4.19 U4.20 | length 9265.7
  L1-Top w10: R19.1@815,2488.62 815,2523 ; v4(1765,238) 1786.62,216.38 R14.1@1810,216.38 ; R16.1@1990,216.38 2021.38,216.38 v4@2025,220
  L1-Top w18: MC1A.7@472.44,2716.54 472.44,2620.56 570,2523 815,2523 912,2523 996.06,2438.94 MC1.7@996.06,2326.18
  L1-Top w20: v2@470,2535 565,2440 R17.1@601.38,2440 ; R15.1@770,3018.62 853.62,3018.62 v4(865,3030) ; v4(2980,758) 2980.62,758.62 R18.1@3050,758.62
  L4-Bottom w20: v4(870,1608) 870,1285 110,525 110,330 202,238 v4(1765,238) 2010,238 v4(2025,223) ; v4@2425,1610 2425,1150 2705,870 2868,870 v4(2980,758)
  L4-Bottom w50: v4(865,3030) 920,3030 980,3090 3415,3090 3785,2720 v4(3785,2555)
  other v2: 470,2533
  other v4: 2425,1613 3785,2485 3785,2520
+3.3VAUX: MC2.69 MC2B.29 | length 1611.8
  L1-Top w8: MC2.69@1972.44,1066.34 v2@1972.44,1108.61
  L1-Top w9.5: v2@1972.44,1108.61 v2(1972.5,1108.68)
  L4-Bottom w10: v2(1972.5,1108.68) 1972.5,1026.5 1985,1014 1985,961 2222,724 2573,724 2686,611 2922,611 3070,463 3070,394.57 MC2B.29@3110.24,354.33
+3.3VDD: C17.2 C19.2 MC1.5 MC1A.5 R1.2 R5.2 R7.2 R8.2 R10.2 R11.2 U5.1 U5.2 U5.19 U5.20 | length 8837.7
  L1-Top w15: MC1A.5@393.7,2716.54 354,2756.24 354,2894 475.75,3015.75 R5.2@708.66,3015.75 ; R1.2@1870,216.38 1871,215.38 v2(1871,184) ; R7.2@1929,215.38 1930,214.38 v2(1930,183) ; R10.2@3109,759.62 v2(3109,788)
  L1-Top w18: MC1A.5@393.7,2716.54 393.7,2531.3 526,2399 943,2399 964.57,2377.43 MC1.5@964.57,2326.18 ; 754.62,2400.38 R8.2@754.62,2441 ; 913.62,2399.62 R11.2@913.62,2441
  L4-Bottom w20: v2(1871,184) 3514,184 3620,290 3620,545 3515,650 3135,650 2997,788 ; 2765,1270 v4(2800,1305) ; 2785,1315 2760,1290 2760,1270 2650,1270 2595,1215 2595,1075 2730,940 2845,940 2997,788 ; v2(3109,788) 2997,788
  L4-Bottom w50: MC1A.5@393.7,2716.54 393.7,2046.3 680,1760 2415,1760 v4(2800,1375)
  other v4: 2800,1340
+5VDC: P1.1 SW3.1 | length 825.4
  L1-Top w100: P1.1@4185.04,2677.17 4197.83,2677.17 4600.69,2274.31 SW3.1@4600.69,2031.39
+5VUSB: MC1.3 MC1A.3 SW3.3 | length 6821.5
  L1-Top w18: 314.96,2646.96 314.96,2467.04 562,2220 876,2220 933.07,2277.07 MC1.3@933.07,2326.18
  L1-Top w50: MC1A.3@314.96,2716.54 314.96,2646.96 279,2611 183,2611 142,2652 142,2819 415,3092 3598,3092 4401,2289 4401,1869.08 SW3.3@4600.69,1669.39
+VDC: C1.2 C4.2 C6.2 C14.2 C16.2 R2.2 R3.2 R9.2 R12.2 R13.2 SW2.1 SW3.2 TP14.1 U1.34 U1.35 U1.36 U1.37 U1.38 U1.39 U1.40 U1.41 U1.42 U1.43 U1.53 U2.15 U2.16 U2.17 U3.15 U3.16 U3.17 U4.15 U4.16 U4.17 U5.15 U5.16 U5.17 | length 3825
  L1-Top w8: v1(2693.23,1175.67) R13.2@2716.85,1175.67 ; v1(2693.23,1963.07) R2.2@2716.85,1963.07 ; v1(3418,1343) R9.2@3418,1374.38 ; v1(3677.48,781.97) R3.2@3701.1,781.97 ; v1(3677.48,2356.77) R12.2@3701.1,2356.77 ; U1.53@3879.15,1777.01 v1@3879.15,1800.35 ; SW2.1@4203,187.25 v1(4203,226)
  L4-Bottom w8: v1(2693.23,1175.67) 2803.07,1175.67 2896.1,1268.7 v4(3050.75,1268.7) ; v1(2693.23,1963.07) 2803.07,1963.07 2896.1,2056.1 v4(3050.75,2056.1) ; v1(3677.48,781.97) 3787.32,781.97 3880.35,875 v4(4035,875) ; v1(3677.48,2356.77) 3787.32,2356.77 3880.35,2449.8 v4(4035,2449.8)
  L4-Bottom w10: v1(4203,226) 4254,175 4425,175 4675,425 4675,1776.08 SW3.2@4600.69,1850.39
  other v1: 3880.04,1797.47
  other v4: 4035,915 4000,935 3050.75,1308.7 3015.75,1328.7 3950,1355 3985,1355 4005,1385 4005,1420 4005,1455 3050.75,2096.1 3015.75,2116.1 4035,2489.8 4000,2509.8
CLKINN: MC2.77 MC2B.37 | length 1763.8
  L1-Top w9.5: MC2.77@2098.43,1066.34 2098.43,1024.44 v1(2098.87,1024)
  L4-Bottom w9.5: v1(2098.87,1024) 2093.37,1018.5 2093.37,996 2125.37,964 2289,964 2330,1005 2503.7,1005 2698.7,810 2875,810 3102,583 3298.04,583 3356.34,524.7 3356.34,510.5 3385.84,481 3385.84,393.69 MC2B.37@3425.2,354.33
CLKINP: MC2.75 MC2B.35 | length 1764.2
  L1-Top w9.5: v1(2066.87,1024) 2066.93,1024.06 MC2.75@2066.93,1066.34
  L4-Bottom w9.5: v1(2066.87,1024) 2072.37,1018.5 2072.37,987.3 2116.67,943 2297.7,943 2338.7,984 2495,984 2690,789 2866.3,789 3093.3,562 3289.34,562 3335.34,516 3335.34,510.5 3305.84,481 3305.84,394.95 MC2B.35@3346.46,354.33
CLKOUT0: MC1.67 MC1B.27 | length 1375.7
  L1-Top w8: MC1.67@1940.95,2326.18 1940.95,2406.95 1999,2465 2910,2465 3031.5,2586.5 MC1B.27@3031.5,2716.54
CLKOUT1: MC1.69 MC1B.29 | length 1421.1
  L1-Top w8: MC1.69@1972.44,2326.18 1972.44,2397.44 2025,2450 2980,2450 3110.24,2580.24 MC1B.29@3110.24,2716.54
CLKOUT2: MC1.71 MC1B.31 | length 1464.7
  L1-Top w8: MC1.71@2003.94,2326.18 2003.94,2385 2053.94,2435 3050,2435 3188.98,2573.98 MC1B.31@3188.98,2716.54
DGND: C1.1 C2.1 C3.1 C4.1 C5.1 C6.1 C7.1 C11.1 C12.1 C13.1 C14.1 C15.1 C16.1 C17.1 C20.1 C21.1 JP1.2 JP1.10 MC1.1 MC1.2 MC1.19 MC1.20 MC1.39 MC1.40 MC1.59 MC1.60 MC1.79 MC1.80 MC1A.1 MC1A.2 MC1A.19 MC1A.20 MC1A.39 MC1A.40 MC1B.19 MC1B.20 MC1B.39 MC1B.40 MC2.1 MC2.2 MC2.19 MC2.20 MC2.39 MC2.40 MC2.59 MC2.60 MC2.79 MC2.80 MC2A.1 MC2A.2 MC2A.19 MC2A.20 MC2A.39 MC2A.40 MC2B.19 MC2B.20 MC2B.39 MC2B.40 P1.2 R6.1 SW1.2 SW2.3 TP16.1 TP18.1 TP20.1 TP21.1 U1.1 U1.2 U1.3 U1.4 U1.27 U1.28 U1.29 U1.30 U1.31 U1.32 U1.33 U1.55 U1.64 U1.65 U1.66 U1.67 U1.68 U1.69 U1.70 U2.0 U2.6 U2.7 U2.8 U2.9 U2.12 U2.18 U3.0 U3.8 U3.10 U3.12 U3.18 U4.0 U4.8 U4.9 U4.11 U4.12 U4.18 U5.0 U5.8 U5.9 U5.10 U5.11 U5.12 U5.18 | length 1071.2
  L1-Top w8: v2@901.58,781.15 MC2.2@901.58,823.43 ; MC2.1@901.58,1066.34 v2@901.58,1108.61 ; v2(901.58,2040.99) MC1.2@901.58,2083.27 ; MC1.1@901.58,2326.18 v2(901.58,2368.46) ; v2@1185.04,781.15 MC2.20@1185.04,823.43 ; MC2.19@1185.04,1066.34 v2@1185.04,1108.61 ; v2(1185.04,2040.99) MC1.20@1185.04,2083.27 ; MC1.19@1185.04,2326.18 v2(1185.04,2368.46) ; v2@1500,781.15 MC2.40@1500,823.43 ; v2(1500,2040.99) MC1.40@1500,2083.27 ; MC1.39@1500,2326.18 v2(1500,2368.46) ; v2@1814.96,781.15 MC2.60@1814.96,823.43 ; MC2.59@1814.96,1066.34 v2@1814.96,1108.61 ; v2(1814.96,2040.99) MC1.60@1814.96,2083.27 ; v2(1814.96,2283.91) MC1.59@1814.96,2326.18 ; MC2.80@2129.92,823.43 v2(2129.92,865.7) ; MC2.79@2129.92,1066.34 v2(2129.92,1108.61) ; v2(2129.92,2040.99) MC1.80@2129.92,2083.27 ; v2(2129.92,2283.91) MC1.79@2129.92,2326.18 ; U1.55@3839.78,1777.01 3839.78,1795.21 v1(3844.04,1799.47) C13.1@3844.04,1825.47 ; R6.1@3847.82,1881.89 v1(3847.82,1908.27) ; C13.1@3848.82,1827.89 R6.1@3848.82,1878.89
  L1-Top w9.5: v2(901.51,781.09) v2@901.58,781.15 ; v2@901.58,1108.61 v2(901.64,1108.68) ; v2(1184.98,781.09) v2@1185.04,781.15 ; v2@1185.04,1108.61 v2(1185.1,1108.68) ; v2(1499.94,781.09) v2@1500,781.15 ; v2(1814.9,781.09) v2@1814.96,781.15 ; v2@1814.96,1108.61 v2(1815.02,1108.68) ; v2(2129.92,865.7) v2@2129.99,865.76 ; v2(2129.92,1108.61) v2@2129.99,1108.68
  L1-Top w15: MC2.39@1500,1066.34 v2(1500,1125) ; SW1.2@3908,187.53 v1(3908,228) ; SW2.3@4379.92,187.01 4381,188.09 v1(4381,227)
  other v1: 980,1005 1043,1005 1105.99,1005 1168.98,1005 1231.98,1005 1294.97,1005 1357.96,1005 1420.95,1005 1483.94,1005 1546.94,1005 1609.93,1005 1672.92,1005 1735.91,1005 1798.91,1005 1893.39,1005 1956.39,1005 2050.87,1005 2113.87,1005 3911.04,1388.47 3891.04,1398.47 3911.04,1408.47 3891.04,1418.47 3911.04,1428.47 3891.04,1438.47 3891.04,1457.21 3339.2,1707.89 3360.2,1707.89 3381.04,1708.47 3401.04,1708.47 3421.04,1708.47 3441.04,1708.47 3461.04,1708.47 3481.04,1708.47 3501.04,1708.47 3591.04,1713.47 3611.04,1713.47 3631.04,1713.47 3651.04,1713.47 3431.04,1723.47 3451.04,1723.47 3471.04,1723.47 3491.04,1723.47 3601.04,1728.47 3621.04,1728.47 3641.04,1728.47 3591.04,1743.47 3611.04,1743.47 3631.04,1743.47 3651.04,1743.47 1232.59,2144.61 1295.58,2144.61 1358.58,2144.61 1421.57,2144.61 1484.56,2144.61 1547.55,2144.61 1610.54,2144.61 1673.54,2144.61 1736.53,2144.61 1799.52,2144.61 1862.51,2144.61 1925.5,2144.61
  other v2: 3897.64,748.03 3937.01,748.03 3976.38,748.03 3897.64,787.4 3937.01,787.4 3976.38,787.4 3897.64,826.77 3937.01,826.77 3976.38,826.77 2913.39,1141.73 2952.76,1141.73 2992.13,1141.73 2913.39,1181.1 2952.76,1181.1 2992.13,1181.1 2913.39,1220.47 2952.76,1220.47 2992.13,1220.47 2913.39,1929.13 2952.76,1929.13 2992.13,1929.13 2913.39,1968.5 2952.76,1968.5 2992.13,1968.5 2913.39,2007.87 2952.76,2007.87 2992.13,2007.87 3897.64,2322.83 3937.01,2322.83 3976.38,2322.83 3897.64,2362.2 3937.01,2362.2 3976.38,2362.2 3897.64,2401.57 3937.01,2401.57 3976.38,2401.57
  other v3: 3811.04,1508.47 3831.04,1508.47 3851.04,1508.47 3871.04,1508.47 3821.04,1523.47 3841.04,1523.47 3861.04,1523.47 3881.04,1523.47 3811.04,1538.47 3831.04,1538.47 3851.04,1538.47 3871.04,1538.47 3821.04,1553.47 3841.04,1553.47 3861.04,1553.47 3881.04,1553.47 3811.04,1568.47 3831.04,1568.47 3851.04,1568.47 3871.04,1568.47 3821.04,1583.47 3841.04,1583.47 3861.04,1583.47 3881.04,1583.47 3811.04,1598.47 3831.04,1598.47 3851.04,1598.47 3871.04,1598.47 3821.04,1613.47 3841.04,1613.47 3861.04,1613.47 3881.04,1613.47 3811.04,1628.47 3831.04,1628.47 3851.04,1628.47 3871.04,1628.47 3821.04,1643.47 3841.04,1643.47 3861.04,1643.47 3881.04,1643.47 3811.04,1658.47 3831.04,1658.47 3851.04,1658.47 3871.04,1658.47 3821.04,1673.47 3841.04,1673.47 3861.04,1673.47 3881.04,1673.47 3811.04,1688.47 3831.04,1688.47 3851.04,1688.47 3871.04,1688.47
JTAG_TCK: JP1.1 MC2.72 MC2B.32 | length 3521.5
  L1-Top w8: MC2.72@2003.94,823.43 2003.94,767.81 2031.75,740 2200,740 2273,813 2273,914 2340,981 2561,981 2707,835 3125,835 3188.98,771.02 MC2B.32@3188.98,433.07 3227,395.05 3227,308 3310,225 3621,225 3764,368 4044,368 4326,650 4482.68,650 JP1.1@4538.19,705.51
JTAG_TDI: JP1.9 MC2.74 MC2B.34 | length 3909.4
  L1-Top w8: MC2.74@2035.43,823.43 2035.43,769.32 2049.75,755 2187,755 2254,822 2254,919 2335,1000 2570,1000 2716,854 3141,854 3267.72,727.28 MC2B.34@3267.72,433.07 3307,393.79 3307,298 3346,259 3604,259 3749,404 4020,404 4373,757 4573,757 4632,816 4632,1011.7 JP1.9@4538.19,1105.51
JTAG_TDO: JP1.3 MC2.78 MC2B.38 | length 3623.2
  L1-Top w8: MC2.78@2098.43,823.43 2098.43,788.32 2105.75,781 2156,781 2209,834 2209,922 2322,1035 2592,1035 2734,893 3172,893 3425.2,639.8 MC2B.38@3425.2,433.07 3467,391.27 3467,326 3482,311 3548,311 3698,461 3972,461 4370,859 4370,926 4400,956 4573,956 4601,928 4601,868.32 JP1.3@4538.19,805.51
JTAG_TMS: JP1.5 MC2.76 MC2B.36 | length 3430.4
  L1-Top w8: MC2.76@2066.93,823.43 2066.93,784.82 2083.75,768 2171,768 2231,828 2231,920 2329,1018 2581,1018 2725,874 3156,874 3346.46,683.54 MC2B.36@3346.46,433.07 3389,390.53 3389,303 3404,288 3578,288 3725,435 3997,435 4414,852 4484.68,852 JP1.5@4538.19,905.51
MC1-A0: MC1.22 MC1A.22 | length 825.6
  L1-Top w8: MC1.22@1216.54,2083.27 v1@1216.54,2125.54
  L1-Top w9.5: v1@1216.54,2125.54 v1(1216.6,2125.61)
  L4-Bottom w8: MC1A.22@1023.62,2795.28 983,2754.65 983,2532 1188.5,2326.5 1188.5,2270.5 1215.59,2243.41 1215.59,2126.62 v1(1216.6,2125.61)
MC1-A1: MC1.21 MC1A.21 | length 470.3
  L1-Top w8: MC1A.21@1023.62,2716.54 1090,2650.16 1090,2620 1216.54,2493.46 MC1.21@1216.54,2326.18
MC1-A2: MC1.42 MC1B.2 | length 927.1
  L1-Top w8: MC1.42@1531.5,2083.27 v2(1531.5,2125.54)
  L4-Bottom w15: v2(1531.5,2125.54) 1510,2147.04 1510,2297.4 MC1B.2@2007.87,2795.28
MC1-A3: MC1.41 MC1B.1 | length 714.4
  L1-Top w8: MC1.41@1531.5,2326.18 1531.5,2456.5 1791.54,2716.54 MC1B.1@2007.87,2716.54
MC1-A4: MC1.62 MC1B.22 | length 1370.7
  L1-Top w9.5: MC1.62@1846.46,2083.27 1846.46,2125.54 v1(1846.52,2125.61)
  L4-Bottom w9.5: v1(1846.52,2125.61) 1844.76,2127.37 1844.76,2221.76 2060,2437 2511,2437 2756,2682 2756,2756 MC1B.22@2795.28,2795.28
MC1-A5: MC1.61 MC1B.21 | length 1180.4
  L1-Top w8: MC1.61@1846.46,2326.18 1846.46,2445.46 1922,2521 2599.74,2521 MC1B.21@2795.28,2716.54
MC1-A6: MC1.68 MC1B.28 | length 1561.2
  L1-Top w9.5: v1(1940.5,2125.61) 1940.95,2125.17 MC1.68@1940.95,2083.27
  L4-Bottom w8: v1(1940.5,2125.61) 1942.5,2127.61 1942.5,2179.5 2014,2251 2249,2251 2343,2157 2465,2157 2993,2685 2993,2756.78 MC1B.28@3031.5,2795.28
MC1-A7: MC1.70 MC1B.30 | length 1604.9
  L1-Top w9.5: MC1.70@1972.44,2083.27 1972.44,2125.54 v1(1972.5,2125.61)
  L4-Bottom w8: v1(1972.5,2125.61) 1971.5,2126.62 1971.5,2172.5 2033,2234 2242,2234 2337,2139 2476,2139 2992,2655 3038,2655 3073,2690 3073,2758.04 MC1B.30@3110.24,2795.28
MC1-ASP0: MC1.4 MC1A.4 | length 1306.6
  L1-Top w8: MC1.4@933.07,2083.27 v1@933.07,2125.54
  L1-Top w9.5: v1@933.07,2125.54 v1(933.13,2125.61)
  L4-Bottom w8: MC1A.4@314.96,2795.28 386.69,2867 633,2867 670,2830 670,2302 776,2196 862.74,2196 v1(933.13,2125.61)
MC1-ASP1: MC1.73 MC1B.33 | length 1510
  L1-Top w8: MC1.73@2035.43,2326.18 2035.43,2380.43 2075,2420 3115,2420 3267.72,2572.72 MC1B.33@3267.72,2716.54
MC1-ASP2: MC1.72 MC1B.32 | length 1663.8
  L1-Top w9.5: v1(2003.5,2125.61) 2003.94,2125.17 MC1.72@2003.94,2083.27
  L4-Bottom w8: v1(2003.5,2125.61) 2003.5,2174.5 2047,2218 2232,2218 2329,2121 2487,2121 3003,2637 3115,2637 3150,2672 3150,2756.3 MC1B.32@3188.98,2795.28
MC1-ASP3: MC1.75 MC1B.35 | length 1551.8
  L1-Top w8: MC1.75@2066.93,2326.18 2066.93,2374.93 2097.98,2405.98 3175.98,2405.98 3346.46,2576.46 MC1B.35@3346.46,2716.54
MC1-ASP4: MC1.74 MC1B.34 | length 1713.8
  L1-Top w9.5: MC1.74@2035.43,2083.27 2035.43,2125.54 v1(2035.5,2125.61)
  L4-Bottom w9.5: v1(2035.5,2125.61) 2035.5,2167.5 2069,2201 2224,2201 2325,2100 2493,2100 3009,2616 3180,2616 3229,2665 3229,2756.56 MC1B.34@3267.72,2795.28
MC1-ASP5: MC1.77 MC1B.37 | length 1596
  L1-Top w8: MC1.77@2098.43,2326.18 2098.43,2368.43 2121.48,2391.48 3241.48,2391.48 3425.2,2575.2 MC1B.37@3425.2,2716.54
MC1-ASP6: MC1.76 MC1B.36 | length 1748.9
  L1-Top w9.5: v1(2066.49,2125.61) 2066.93,2125.17 MC1.76@2066.93,2083.27
  L4-Bottom w9.5: v1(2066.49,2125.61) 2066.49,2158.49 2092,2184 2210,2184 2313,2081 2504,2081 3022,2599 3226,2599 3305,2678 3305,2753.82 MC1B.36@3346.46,2795.28
MC1-ASP7: MC1.78 MC1B.38 | length 1802
  L1-Top w9.5: MC1.78@2098.43,2083.27 2098.43,2125.54 v1(2098.49,2125.61)
  L4-Bottom w9.5: v1(2098.49,2125.61) 2098.49,2151.49 2115,2168 2194,2168 2299,2063 2512,2063 3032,2583 3304,2583 3387,2666 3387,2757.08 MC1B.38@3425.2,2795.28
MC1-BN0: MC1.26 MC1A.26 | length 807.8
  L1-Top w9.5: MC1.26@1279.53,2083.27 1279.53,2125.54 v1(1279.59,2125.61)
  L4-Bottom w9.5: MC1A.26@1181.1,2795.28 1141.54,2755.72 1141.54,2680 1114.78,2653.24 1114.78,2535 1233,2416.78 1233,2286 1274.09,2244.91 1274.09,2131.11 v1(1279.59,2125.61)
MC1-BN1: MC1.25 MC1A.25 | length 454.4
  L1-Top w9.5: MC1A.25@1181.1,2716.54 1153,2688.43 1153,2667 1274.28,2545.72 1274.28,2364.72 1279.53,2359.48 MC1.25@1279.53,2326.18
MC1-BN2: MC1.30 MC1A.30 | length 768.6
  L1-Top w9.5: MC1.30@1342.52,2083.27 1342.52,2125.54 v1(1342.58,2125.61)
  L4-Bottom w9.5: MC1A.30@1338.58,2795.28 1299.02,2755.72 1299.02,2685 1272.26,2658.24 1272.26,2344.74 1337.08,2279.92 1337.08,2131.11 v1(1342.58,2125.61)
MC1-BN3: MC1.29 MC1A.29 | length 415.9
  L1-Top w9.5: MC1A.29@1338.58,2716.54 1309.71,2687.67 1309.71,2645 1337.27,2617.44 1337.27,2364.72 1342.52,2359.48 MC1.29@1342.52,2326.18
MC1-BN4: MC1.34 MC1A.34 | length 754.1
  L1-Top w9.5: MC1.34@1405.51,2083.27 v1(1405.58,2125.61) v1(1405.58,2125.61)
  L4-Bottom w9.5: v1(1405.58,2125.61) 1400.08,2131.11 1400.08,2179.7 1400,2179.77 1400,2551.3 1429.74,2581.05 1429.74,2651.24 1456.51,2678 1456.51,2755.72 MC1A.34@1496.06,2795.28
MC1-BN5: MC1.33 MC1A.33 | length 432.2
  L1-Top w9.5: MC1.33@1405.51,2326.18 1405.51,2359.48 1400.26,2364.72 1400.26,2545.26 1466,2611 1466,2686.47 MC1A.33@1496.06,2716.54
MC1-BN6: MC1.38 MC1A.38 | length 793.3
  L1-Top w9.5: MC1.38@1468.5,2083.27 v1(1468.57,2125.61) v1(1468.57,2125.61)
  L4-Bottom w9.5: v1(1468.57,2125.61) 1463.07,2131.11 1463.07,2212.7 1463,2212.77 1463,2491.3 1587.22,2615.53 1587.22,2651.24 1613.99,2678 1613.99,2755.72 MC1A.38@1653.54,2795.28
MC1-BN7: MC1.37 MC1A.37 | length 471.3
  L1-Top w9.5: MC1.37@1468.5,2326.18 1468.5,2359.48 1463.26,2364.72 1463.26,2383 1463.26,2471.56 1623,2631.3 1623,2685.99 MC1A.37@1653.54,2716.54
MC1-BN8: MC1.46 MC1B.6 | length 1049.7
  L1-Top w9.5: MC1.46@1594.49,2083.27 v1(1594.55,2125.61) v1(1594.55,2125.61)
  L4-Bottom w9.5: v1(1594.55,2125.61) 1589.05,2131.11 1589.05,2282.05 1898,2591 2063,2591 2099.04,2627.04 2099.04,2648.24 2125.8,2675 2125.8,2755.72 MC1B.6@2165.35,2795.28
MC1-BN9: MC1.45 MC1B.5 | length 812.1
  L1-Top w9.5: MC1.45@1594.49,2326.18 1594.49,2359.48 1589.24,2364.72 1589.24,2449.24 1799,2659 2090,2659 2147.54,2716.54 MC1B.5@2165.35,2716.54
MC1-BN10: MC1.50 MC1B.10 | length 1145.1
  L1-Top w9.5: MC1.50@1657.48,2083.27 v1(1657.54,2125.61) v1(1657.54,2125.61)
  L4-Bottom w9.5: v1(1657.54,2125.61) 1652.04,2131.11 1652.04,2280.04 1913,2541 2175.21,2541 2256.52,2622.3 ; 2256.52,2623 2256.52,2653.24 2283.28,2680 2283.28,2755.72 MC1B.10@2322.84,2795.28
MC1-BN11: MC1.49 MC1B.9 | length 917.9
  L1-Top w9.5: MC1.49@1657.48,2326.18 1657.48,2359.48 1652.23,2364.72 1652.23,2442.23 1830,2620 2252.66,2620 2293.97,2661.3 2293.97,2687.67 MC1B.9@2322.84,2716.54
MC1-BN12: MC1.54 MC1B.14 | length 1220.9
  L1-Top w9.5: MC1.54@1720.47,2083.27 1720.47,2125.54 v1(1720.54,2125.61)
  L4-Bottom w9.5: v1(1720.54,2125.61) 1715.04,2131.11 1715.04,2257.04 1959,2501 2282.69,2501 2414,2632.3 2414,2652.24 2440.76,2679 2440.76,2755.72 MC1B.14@2480.32,2795.28
MC1-BN13: MC1.53 MC1B.13 | length 1002.7
  L1-Top w9.5: MC1.53@1720.47,2326.18 1720.47,2359.48 1715.22,2364.72 1715.22,2429.22 1862.98,2576.98 2363.68,2576.98 2449,2662.3 2449,2685.22 MC1B.13@2480.32,2716.54
MC1-BN14: MC1.58 MC1B.18 | length 1270.5
  L1-Top w9.5: MC1.58@1783.46,2083.27 1783.46,2125.54 v1(1783.53,2125.61)
  L4-Bottom w9.5: v1(1783.53,2125.61) 1778.03,2131.11 1778.03,2185.33 2051.7,2459 2393.17,2459 2571.48,2637.3 2571.48,2650.24 2598.24,2677 2598.24,2755.72 MC1B.18@2637.8,2795.28
MC1-BN15: MC1.57 MC1B.17 | length 1089.3
  L1-Top w9.5: MC1.57@1783.46,2326.18 1783.46,2359.48 1778.22,2364.72 1778.22,2417.22 1901.98,2540.98 2483.68,2540.98 2608,2665.3 2608,2686.74 MC1B.17@2637.8,2716.54
MC1-BN16: MC1.66 MC1B.26 | length 1485
  L1-Top w9.5: MC1.66@1909.45,2083.27 1909.45,2125.54 v1(1909.51,2125.61)
  L4-Bottom w9.5: v1(1909.51,2125.61) 1904.01,2131.11 1904.01,2221.01 2080,2397 2654.14,2397 2713.14,2456 2886.44,2629.3 2886.44,2657.24 2913.2,2684 2913.2,2755.72 MC1B.26@2952.76,2795.28
MC1-BN17: MC1.65 MC1B.25 | length 1290.6
  L1-Top w9.5: MC1.65@1909.45,2326.18 1909.45,2359.48 1904.2,2364.72 1904.2,2434.2 1953,2483 2744.7,2483 2921,2659.3 2921,2684.78 MC1B.25@2952.76,2716.54
MC1-BP0: MC1.24 MC1A.24 | length 806.2
  L1-Top w9.5: v1(1247.59,2125.61) 1248.03,2125.17 MC1.24@1248.03,2083.27
  L4-Bottom w9.5: MC1A.24@1102.36,2795.28 1067.02,2759.94 1067.02,2680 1093.78,2653.24 1093.78,2526.3 1212,2408.09 1212,2277.3 1253.09,2236.21 1253.09,2131.11 v1(1247.59,2125.61)
MC1-BP1: MC1.23 MC1A.23 | length 455
  L1-Top w9.5: MC1A.23@1102.36,2716.54 1132,2686.9 1132,2658.3 1253.28,2537.02 1253.28,2364.72 1248.03,2359.48 MC1.23@1248.03,2326.18
MC1-BP2: MC1.28 MC1A.28 | length 767
  L1-Top w9.5: v1(1310.58,2125.61) 1311.02,2125.17 MC1.28@1311.02,2083.27
  L4-Bottom w9.5: MC1A.28@1259.84,2795.28 1224.5,2759.94 1224.5,2685 1251.26,2658.24 1251.26,2336.04 1316.08,2271.22 1316.08,2131.11 v1(1310.58,2125.61)
MC1-BP3: MC1.27 MC1A.27 | length 415.9
  L1-Top w9.5: MC1A.27@1259.84,2716.54 1288.71,2687.67 1288.71,2636.3 1316.27,2608.74 1316.27,2364.72 1311.02,2359.48 MC1.27@1311.02,2326.18
MC1-BP4: MC1.32 MC1A.32 | length 752.5
  L1-Top w9.5: v1(1373.58,2125.61) 1374.02,2125.17 MC1.32@1374.02,2083.27
  L4-Bottom w9.5: v1(1373.58,2125.61) 1379.08,2131.11 1379.08,2171 1379,2171.08 1379,2497.7 1379,2560 1408.74,2589.74 1408.74,2651.24 1381.98,2678 1381.98,2759.94 MC1A.32@1417.32,2795.28
MC1-BP5: MC1.31 MC1A.31 | length 431.2
  L1-Top w9.5: MC1.31@1374.02,2326.18 1374.02,2359.48 1379.26,2364.72 1379.26,2553.96 1445,2619.7 1445,2688.86 MC1A.31@1417.32,2716.54
MC1-BP6: MC1.36 MC1A.36 | length 791.7
  L1-Top w9.5: v1(1436.57,2125.61) 1437.01,2125.17 MC1.36@1437.01,2083.27
  L4-Bottom w9.5: v1(1436.57,2125.61) 1442.07,2131.11 1442.07,2204 1442,2204.07 1442,2430.7 1442,2500 1566.22,2624.22 1566.22,2651.24 1539.46,2678 1539.46,2759.94 MC1A.36@1574.8,2795.28
MC1-BP7: MC1.35 MC1A.35 | length 470
  L1-Top w9.5: MC1.35@1437.01,2326.18 1437.01,2359.48 1442.26,2364.72 1442.26,2391.7 1442.26,2480.26 1602,2640 1602,2689.34 MC1A.35@1574.8,2716.54
MC1-BP8: MC1.44 MC1B.4 | length 1048.1
  L1-Top w9.5: v1(1562.55,2125.61) 1562.99,2125.17 MC1.44@1562.99,2083.27
  L4-Bottom w9.5: v1(1562.55,2125.61) 1568.05,2131.11 1568.05,2290.75 1889.3,2612 2054.3,2612 2078.04,2635.73 2078.04,2648.24 2051.27,2675 2051.27,2759.94 MC1B.4@2086.61,2795.28
MC1-BP9: MC1.43 MC1B.3 | length 776.9
  L1-Top w9.5: MC1.43@1562.99,2326.18 1562.99,2359.48 1568.24,2364.72 1568.24,2457.94 1790.3,2680 2080,2680 2086.61,2686.61 MC1B.3@2086.61,2716.54
MC1-BP10: MC1.48 MC1B.8 | length 1144.2
  L1-Top w9.5: v1(1625.54,2125.61) 1625.98,2125.17 MC1.48@1625.98,2083.27
  L4-Bottom w9.5: v1(1625.54,2125.61) 1631.04,2131.11 1631.04,2288.74 1904.3,2562 2166.52,2562 2235.52,2631 2235.52,2653.24 2208.75,2680 2208.75,2759.94 MC1B.8@2244.1,2795.28
MC1-BP11: MC1.47 MC1B.7 | length 917.9
  L1-Top w9.5: MC1.47@1625.98,2326.18 1625.98,2359.48 1631.23,2364.72 1631.23,2450.93 1821.3,2641 2243.97,2641 2272.97,2670 2272.97,2687.67 MC1B.7@2244.1,2716.54
MC1-BP12: MC1.52 MC1B.12 | length 1219.3
  L1-Top w9.5: v1(1688.54,2125.61) 1688.98,2125.17 MC1.52@1688.98,2083.27
  L4-Bottom w9.5: v1(1688.54,2125.61) 1694.04,2131.11 1694.04,2265.73 1950.3,2522 2274,2522 2393,2641 2393,2652.24 2366.23,2679 2366.23,2759.94 MC1B.12@2401.58,2795.28
MC1-BP13: MC1.51 MC1B.11 | length 1000.7
  L1-Top w9.5: MC1.51@1688.98,2326.18 1688.98,2359.48 1694.22,2364.72 1694.22,2437.92 1854.29,2597.98 2354.98,2597.98 2428,2671 2428,2690.11 MC1B.11@2401.58,2716.54
MC1-BP14: MC1.56 MC1B.16 | length 1268.9
  L1-Top w9.5: v1(1751.53,2125.61) 1751.97,2125.17 MC1.56@1751.97,2083.27
  L4-Bottom w9.5: v1(1751.53,2125.61) 1757.03,2131.11 1757.03,2194.03 2043,2480 2384.48,2480 2550.48,2646 2550.48,2650.24 2523.72,2677 2523.72,2759.94 MC1B.16@2559.06,2795.28
MC1-BP15: MC1.55 MC1B.15 | length 1088.6
  L1-Top w9.5: MC1.55@1751.97,2326.18 1751.97,2359.48 1757.22,2364.72 1757.22,2425.92 1893.29,2561.98 2474.98,2561.98 2587,2674 2587,2688.59 MC1B.15@2559.06,2716.54
MC1-BP16: MC1.64 MC1B.24 | length 1483.4
  L1-Top w9.5: v1(1877.51,2125.61) 1877.95,2125.17 MC1.64@1877.95,2083.27
  L4-Bottom w9.5: v1(1877.51,2125.61) 1883.01,2131.11 1883.01,2229.71 2071.3,2418 2645.44,2418 2704.44,2477 2865.44,2638 2865.44,2657.24 2838.68,2684 2838.68,2759.94 MC1B.24@2874.02,2795.28
MC1-BP17: MC1.63 MC1B.23 | length 1288.2
  L1-Top w9.5: MC1.63@1877.95,2326.18 1877.95,2359.48 1883.2,2364.72 1883.2,2442.9 1944.3,2504 2736,2504 2900,2668 2900,2690.55 MC1B.23@2874.02,2716.54
MC2-A0: MC2.6 MC2A.6 | length 797.3
  L1-Top w8: MC2A.6@393.7,433.07 393.7,489.7 640,736 931,736 964.57,769.57 MC2.6@964.57,823.43
MC2-A1: MC2.5 MC2A.5 | length 948.5
  L1-Top w8: v1@964.57,1024.06 MC2.5@964.57,1066.34
  L1-Top w9.5: v1(964.5,1024) v1@964.57,1024.06
  L4-Bottom w8: MC2A.5@393.7,354.33 435,395.63 435,494.5 v1(964.5,1024)
MC2-A2: MC2.22 MC2A.22 | length 470.3
  L1-Top w8: MC2A.22@1023.62,433.07 1023.62,518.62 1216.54,711.54 MC2.22@1216.54,823.43
MC2-A3: MC2.21 MC2A.21 | length 791.9
  L1-Top w8: v1@1216.54,1024.06 MC2.21@1216.54,1066.34
  L1-Top w9.5: v1(1216.47,1024) v1@1216.54,1024.06
  L4-Bottom w8: MC2A.21@1023.62,354.33 1067.77,398.48 1067.77,703.77 1214.98,850.98 1214.98,1022.5 v1(1216.47,1024)
MC2-A4: MC2.62 MC2B.22 | length 1189.9
  L1-Top w8: MC2.62@1846.46,823.43 1846.46,748.54 1952,643 2646,643 2795.28,493.72 MC2B.22@2795.28,433.07
MC2-A5: MC2.61 MC2B.21 | length 1340
  L1-Top w8: v1@1846.46,1024.06 MC2.61@1846.46,1066.34
  L1-Top w9.5: v1(1846.39,1024) v1@1846.46,1024.06
  L4-Bottom w8: v1(1846.39,1024) 1846.39,963.61 2156,654 2432,654 2597,489 2722,489 2757,454 2757,392.61 MC2B.21@2795.28,354.33
MC2-A6: MC2.64 MC2B.24 | length 1239.3
  L1-Top w8: MC2.64@1877.95,823.43 1877.95,742.05 1964,656 2709,656 2874.02,490.98 MC2B.24@2874.02,433.07
MC2-A7: MC2.63 MC2B.23 | length 1388.9
  L1-Top w8: v1@1877.95,1024.06 MC2.63@1877.95,1066.34
  L1-Top w9.5: v1(1877.89,1024) v1@1877.95,1024.06
  L4-Bottom w8: v1(1877.89,1024) 1876.39,1022.5 1876.39,968.61 2174,671 2442,671 2607,506 2788,506 2835,459 2835,393.35 MC2B.23@2874.02,354.33
MC2-ASP0: MC2.71 MC2B.31 | length 1565.5
  L1-Top w8: v1@2003.94,1024.06 MC2.71@2003.94,1066.34
  L1-Top w9.5: v1(2003.87,1024) v1@2003.94,1024.06
  L4-Bottom w8: v1(2003.87,1024) 2003.87,981.13 2080,905 2130,905 2297,738 2833,738 3077,494 3110,494 3149,455 3149,394.31 MC2B.31@3188.98,354.33
MC2-ASP1: MC2.73 MC2B.33 | length 1626.5
  L1-Top w8: v1@2035.43,1024.44 MC2.73@2035.43,1066.34
  L1-Top w9.5: v1@2035.43,1024.44 v1(2035.87,1024)
  L4-Bottom w8: v1(2035.87,1024) 2033.87,1022 2033.87,980.13 2093,921 2150,921 2317,754 2851,754 3086,519 3182,519 3228,473 3228,394.05 MC2B.33@3267.72,354.33
MC2-BN0: MC2.10 MC2A.10 | length 747.6
  L1-Top w9.5: MC2A.10@551.18,433.07 525,459.25 525,495 718,688 954.01,688 1022.31,756.3 1022.31,784.88 1027.56,790.13 MC2.10@1027.56,823.43
MC2-BN1: MC2.9 MC2A.9 | length 931.9
  L1-Top w9.5: MC2.9@1027.56,1066.34 1027.56,1024.44 v1(1028,1024)
  L4-Bottom w9.5: MC2A.9@551.18,354.33 586.52,389.67 586.52,467 559.76,493.76 559.76,529.62 1022.5,992.36 1022.5,1018.5 v1(1028,1024)
MC2-BN2: MC2.14 MC2A.14 | length 671.6
  L1-Top w9.5: MC2A.14@708.66,433.07 681,460.73 681,505 815,639 986,639 1085.3,738.3 1085.3,784.88 1090.55,790.13 MC2.14@1090.55,823.43
MC2-BN3: MC2.13 MC2A.13 | length 892.7
  L1-Top w9.5: MC2.13@1090.55,1066.34 1090.55,1024.44 v1(1090.99,1024)
  L4-Bottom w9.5: MC2A.13@708.66,354.33 744,389.67 744,454 717.24,480.76 717.24,497.24 1085.49,865.49 1085.49,1018.5 v1(1090.99,1024)
MC2-BN4: MC2.18 MC2A.18 | length 593.1
  L1-Top w9.5: MC2A.18@866.14,433.07 837.27,461.94 837.27,515.27 900,578 1002,578 1148.3,724.3 1148.3,784.88 1153.54,790.13 MC2.18@1153.54,823.43
MC2-BN5: MC2.17 MC2A.17 | length 853.6
  L1-Top w9.5: MC2.17@1153.54,1066.34 1153.54,1024.44 v1(1153.98,1024)
  L4-Bottom w9.5: MC2A.17@866.14,354.33 901.48,389.67 901.48,457 874.72,483.76 874.72,565.02 1148.48,838.79 1148.48,1018.5 v1(1153.98,1024)
MC2-BN6: MC2.26 MC2A.26 | length 452.7
  L1-Top w9.5: MC2A.26@1181.1,433.07 1155,459.17 1155,550.3 1274.28,669.58 1274.28,784.88 1279.53,790.13 MC2.26@1279.53,823.43
MC2-BN7: MC2.25 MC2A.25 | length 775.3
  L1-Top w9.5: MC2.25@1279.53,1066.34 1279.53,1024.44 v1(1279.97,1024)
  L4-Bottom w9.5: MC2A.25@1181.1,354.33 1216.44,389.67 1216.44,460 1189.68,486.76 1189.68,509.68 1274.47,594.47 1274.47,1018.5 v1(1279.97,1024)
MC2-BN8: MC2.30 MC2A.30 | length 412.5
  L1-Top w9.5: MC2A.30@1338.58,433.07 1313.85,457.81 1313.85,554.15 1337.27,577.57 1337.27,784.88 1342.52,790.13 MC2.30@1342.52,823.43
MC2-BN9: MC2.29 MC2A.29 | length 744.2
  L1-Top w9.5: MC2.29@1342.52,1066.34 1342.52,1024.44 v1(1342.96,1024)
  L4-Bottom w9.5: MC2A.29@1338.58,354.33 1373.92,389.67 1373.92,464.24 1337.46,500.7 1337.46,1018.5 v1(1342.96,1024)
MC2-BN10: MC2.34 MC2A.34 | length 432.2
  L1-Top w9.5: MC2.34@1405.51,823.43 1405.51,790.13 1400.26,784.88 1400.26,627.74 1468,560 1468,461.13 MC2A.34@1496.06,433.07
MC2-BN11: MC2.33 MC2A.33 | length 783.3
  L1-Top w9.5: MC2.33@1405.51,1066.34 1405.51,1024.44 v1(1405.95,1024)
  L4-Bottom w9.5: v1(1405.95,1024) 1400.45,1018.5 1400.45,586.55 1531.4,455.6 1531.4,389.67 MC2A.33@1496.06,354.33
MC2-BN12: MC2.38 MC2A.38 | length 471.3
  L1-Top w9.5: MC2.38@1468.5,823.43 1468.5,790.13 1463.26,784.88 1463.26,658.74 1624.67,497.33 1624.67,461.94 MC2A.38@1653.54,433.07
MC2-BN13: MC2.37 MC2A.37 | length 849
  L1-Top w9.5: MC2.37@1468.5,1066.34 1468.5,1024.44 v1(1468.94,1024)
  L4-Bottom w9.5: v1(1468.94,1024) 1463.44,1018.5 1463.44,640.25 1614.81,488.88 1660,488.88 1688.88,460 1688.88,389.67 MC2A.37@1653.54,354.33
MC2-BN14: MC2.46 MC2B.6 | length 807.8
  L1-Top w9.5: MC2.46@1594.49,823.43 1594.49,790.13 1589.24,784.88 1589.24,725.46 1812.7,502 2114.18,502 2136.48,479.7 2136.48,461.94 MC2B.6@2165.35,433.07
MC2-BN15: MC2.45 MC2B.5 | length 1115.3
  L1-Top w9.5: MC2.45@1594.49,1066.34 1594.49,1024.44 v1(1594.93,1024)
  L4-Bottom w9.5: v1(1594.93,1024) 1589.43,1018.5 1589.43,943.57 1675,858 1675,641 1809.5,506.5 2086.5,506.5 2126,467 2126,393.69 MC2B.5@2165.35,354.33
MC2-BN16: MC2.50 MC2B.10 | length 893.5
  L1-Top w9.5: MC2.50@1657.48,823.43 1657.48,790.13 1652.23,784.88 1652.23,742.47 1851.7,543 2232.66,543 2293.97,481.7 2293.97,461.94 MC2B.10@2322.84,433.07
MC2-BN17: MC2.49 MC2B.9 | length 1182.7
  L1-Top w9.5: MC2.49@1657.48,1066.34 1657.48,1024.44 v1(1657.92,1024)
  L4-Bottom w9.5: v1(1657.92,1024) 1652.42,1018.5 1652.42,998.58 1750,901 1750,657.7 1852.7,555 2178,555 2283.48,449.52 2283.48,393.69 MC2B.9@2322.84,354.33
MC2-BN18: MC2.54 MC2B.14 | length 1017.4
  L1-Top w9.5: MC2.54@1720.47,823.43 1720.47,790.13 1715.22,784.88 1715.22,754.78 1886,584 2411.7,584 2450,545.7 2450,463.39 MC2B.14@2480.32,433.07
